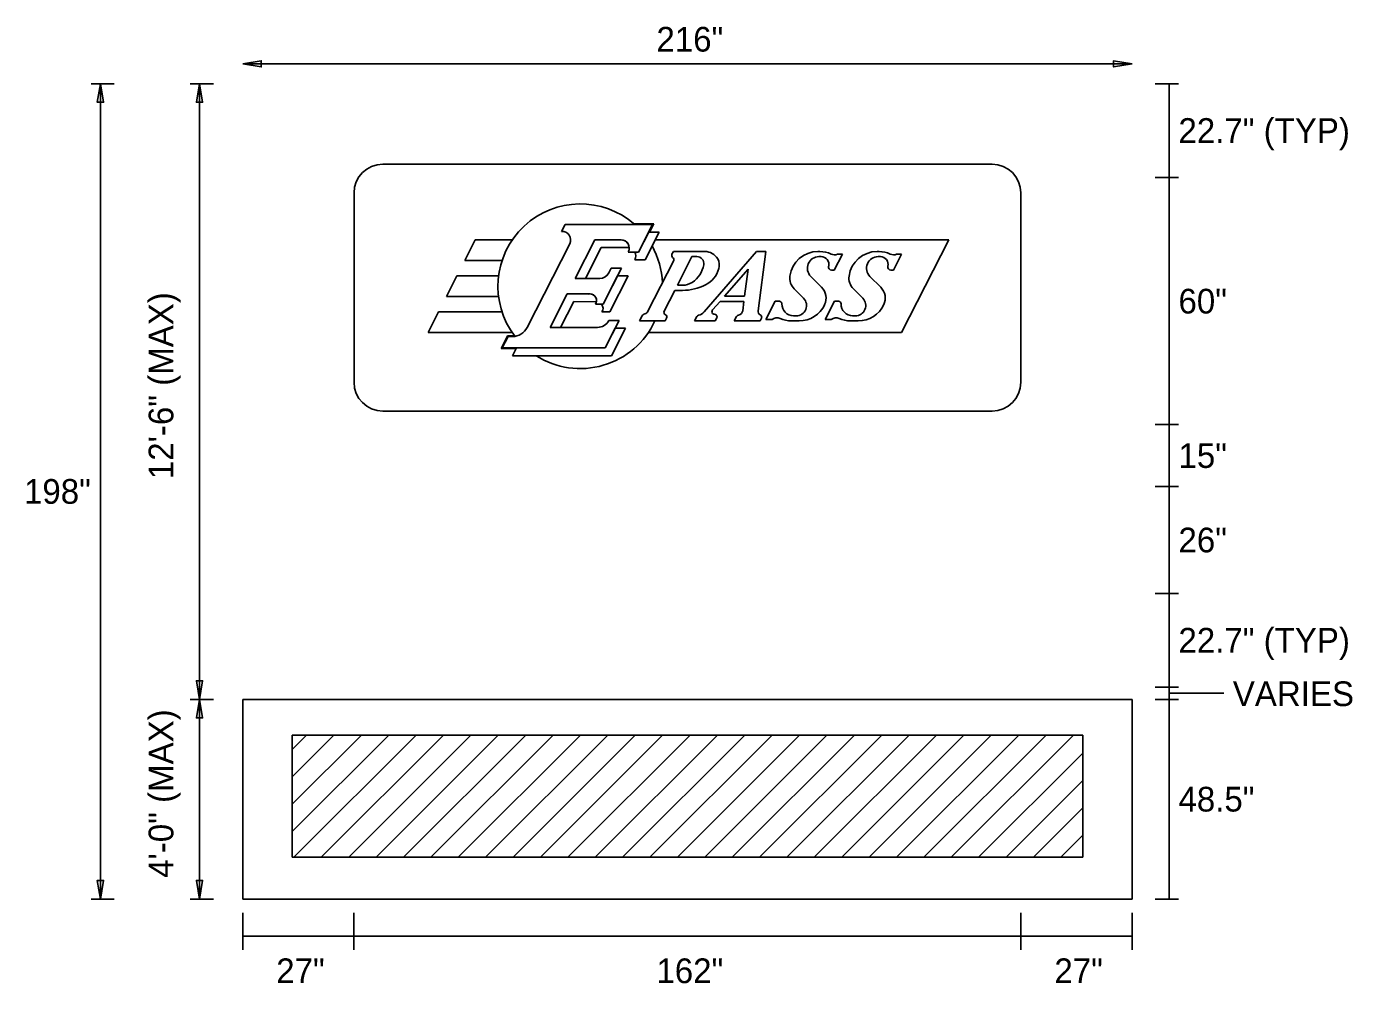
# Model space of a CAD drawing. Extents: x 10268312 to 10268706, y 2142548 to 2142786.
# Drawn here: x 10268425.68 to 10268465.55, y 2142704.58 to 2142733.35 of the extents above; entities that cross this region are included whole.
import ezdxf

# ---------------------------------------------------------------- set-up
doc = ezdxf.new("R2010")
doc.units = 0
for name, color, linetype in [('GSDims', 7, 'Continuous'), ('SignPanel', 7, 'Continuous'), ('TextMisc', 7, 'Continuous')]:
    doc.layers.add(name, color=color, linetype=linetype)

msp = doc.modelspace()

# ---------------------------------------------------------------- linework, layer by layer
at = {"layer": 'GSDims'}
for p, q in [((10268432.186, 2142732.227), (10268458.924, 2142732.227)), ((10268428.323, 2142731.624), (10268427.626, 2142731.624)), ((10268427.905, 2142707.115), (10268427.905, 2142731.624)), ((10268431.303, 2142731.624), (10268430.607, 2142731.624)), ((10268430.886, 2142713.118), (10268430.886, 2142731.624)), ((10268459.62, 2142731.624), (10268460.317, 2142731.624)), ((10268460.038, 2142728.814), (10268460.038, 2142731.624)), ((10268460.317, 2142731.624), (10268460.317, 2142731.624)), ((10268459.62, 2142728.802), (10268460.317, 2142728.802)), ((10268460.038, 2142721.377), (10268460.038, 2142728.814)), ((10268459.62, 2142721.377), (10268460.317, 2142721.377)), ((10268460.038, 2142719.518), (10268460.038, 2142721.377)), ((10268459.62, 2142719.518), (10268460.317, 2142719.518)), ((10268460.038, 2142719.518), (10268460.038, 2142716.299)), ((10268459.62, 2142716.299), (10268460.317, 2142716.299)), ((10268460.038, 2142713.489), (10268460.038, 2142716.299)), ((10268459.62, 2142713.489), (10268460.317, 2142713.489)), ((10268460.038, 2142713.118), (10268460.038, 2142713.489)), ((10268431.303, 2142713.118), (10268430.607, 2142713.118)), ((10268430.886, 2142707.115), (10268430.886, 2142713.118)), ((10268459.62, 2142713.118), (10268460.317, 2142713.118)), ((10268460.038, 2142713.304), (10268461.681, 2142713.304)), ((10268460.038, 2142707.115), (10268460.038, 2142713.118)), ((10268428.323, 2142707.115), (10268427.626, 2142707.115)), ((10268431.303, 2142707.115), (10268430.607, 2142707.115)), ((10268459.62, 2142707.115), (10268460.317, 2142707.115)), ((10268432.186, 2142706.697), (10268432.186, 2142705.583)), ((10268435.528, 2142706.697), (10268435.528, 2142705.583)), ((10268455.582, 2142706.697), (10268455.582, 2142705.583)), ((10268458.924, 2142706.697), (10268458.924, 2142705.583)), ((10268432.186, 2142706), (10268435.528, 2142706)), ((10268435.528, 2142706), (10268455.582, 2142706)), ((10268455.582, 2142706), (10268458.924, 2142706))]:
    msp.add_line(p, q, dxfattribs=at)
for points in [[(10268432.186, 2142732.227), (10268432.743, 2142732.134), (10268432.743, 2142732.319)], [(10268458.924, 2142732.227), (10268458.367, 2142732.134), (10268458.367, 2142732.319)], [(10268427.905, 2142731.624), (10268427.998, 2142731.067), (10268427.812, 2142731.067)], [(10268430.886, 2142731.624), (10268430.978, 2142731.067), (10268430.793, 2142731.067)], [(10268430.886, 2142713.118), (10268430.978, 2142713.675), (10268430.793, 2142713.675)], [(10268430.886, 2142713.118), (10268430.978, 2142712.561), (10268430.793, 2142712.561)], [(10268427.905, 2142707.115), (10268427.998, 2142707.672), (10268427.812, 2142707.672)], [(10268430.886, 2142707.115), (10268430.978, 2142707.672), (10268430.793, 2142707.672)]]:
    msp.add_lwpolyline(points, close=True, dxfattribs=at)
at = {"layer": 'SignPanel'}
for p, q in [((10268436.397, 2142729.21), (10268454.713, 2142729.21)), ((10268435.531, 2142722.651), (10268435.531, 2142728.344)), ((10268455.579, 2142728.344), (10268455.579, 2142722.651)), ((10268441.772, 2142727.187), (10268441.877, 2142727.395)), ((10268441.877, 2142727.395), (10268444.507, 2142727.395)), ((10268443.942, 2142727.418), (10268444.545, 2142727.418)), ((10268444.507, 2142727.395), (10268444.086, 2142726.567)), ((10268444.545, 2142727.418), (10268444.415, 2142727.163)), ((10268439.176, 2142726.93), (10268438.861, 2142726.312)), ((10268439.176, 2142726.93), (10268440.285, 2142726.93)), ((10268442.768, 2142726.93), (10268442.177, 2142725.77)), ((10268442.177, 2142725.77), (10268442.768, 2142726.93)), ((10268443.557, 2142726.93), (10268442.768, 2142726.93)), ((10268442.768, 2142726.93), (10268443.557, 2142726.93)), ((10268444.085, 2142726.567), (10268444.389, 2142727.163)), ((10268444.701, 2142727.163), (10268444.28, 2142726.335)), ((10268444.389, 2142727.163), (10268444.701, 2142727.163)), ((10268444.583, 2142726.93), (10268453.408, 2142726.93)), ((10268451.989, 2142724.146), (10268453.408, 2142726.93)), ((10268440.732, 2142724.297), (10268442.016, 2142726.817)), ((10268442.963, 2142726.699), (10268442.49, 2142725.77)), ((10268443.804, 2142726.699), (10268442.963, 2142726.699)), ((10268444.086, 2142726.567), (10268443.776, 2142726.567)), ((10268443.97, 2142726.567), (10268444.085, 2142726.567)), ((10268445.132, 2142726.582), (10268445.089, 2142726.5)), ((10268446.079, 2142726.582), (10268445.132, 2142726.582)), ((10268446.055, 2142724.766), (10268447.635, 2142726.582)), ((10268447.635, 2142726.582), (10268447.913, 2142726.582)), ((10268447.913, 2142726.582), (10268447.682, 2142724.802)), ((10268449.478, 2142726.582), (10268449.536, 2142726.582)), ((10268450.214, 2142726.505), (10268449.968, 2142726.022)), ((10268450.098, 2142726.505), (10268450.214, 2142726.505)), ((10268451.257, 2142726.582), (10268451.316, 2142726.582)), ((10268451.993, 2142726.505), (10268451.747, 2142726.022)), ((10268451.877, 2142726.505), (10268451.993, 2142726.505)), ((10268438.861, 2142726.312), (10268439.98, 2142726.312)), ((10268444.28, 2142726.335), (10268443.971, 2142726.335)), ((10268445.134, 2142726.29), (10268444.368, 2142724.787)), ((10268445.253, 2142725.569), (10268445.69, 2142726.428)), ((10268445.253, 2142725.569), (10268445.69, 2142726.428)), ((10268445.69, 2142726.428), (10268445.839, 2142726.428)), ((10268445.69, 2142726.428), (10268445.839, 2142726.428)), ((10268449.576, 2142726.428), (10268449.509, 2142726.428)), ((10268451.355, 2142726.428), (10268451.288, 2142726.428)), ((10268438.625, 2142725.848), (10268438.309, 2142725.229)), ((10268438.625, 2142725.848), (10268439.875, 2142725.848)), ((10268442.177, 2142725.77), (10268442.918, 2142725.77)), ((10268442.49, 2142725.77), (10268442.177, 2142725.77)), ((10268443.574, 2142726.08), (10268443.022, 2142724.997)), ((10268443.022, 2142724.997), (10268443.456, 2142725.848)), ((10268443.193, 2142725.939), (10268443.265, 2142726.08)), ((10268443.768, 2142725.848), (10268443.217, 2142724.765)), ((10268443.265, 2142726.08), (10268443.574, 2142726.08)), ((10268443.456, 2142725.848), (10268443.768, 2142725.848)), ((10268447.376, 2142726.049), (10268446.669, 2142725.236)), ((10268447.376, 2142726.049), (10268446.669, 2142725.236)), ((10268447.27, 2142725.236), (10268447.376, 2142726.049)), ((10268447.27, 2142725.236), (10268447.376, 2142726.049)), ((10268449.263, 2142725.834), (10268449.587, 2142725.509)), ((10268449.968, 2142726.022), (10268449.891, 2142726.022)), ((10268451.042, 2142725.834), (10268451.367, 2142725.509)), ((10268451.747, 2142726.022), (10268451.669, 2142726.022)), ((10268441.941, 2142725.306), (10268441.429, 2142724.301)), ((10268441.429, 2142724.301), (10268441.941, 2142725.306)), ((10268442.62, 2142725.306), (10268441.941, 2142725.306)), ((10268441.941, 2142725.306), (10268442.591, 2142725.304)), ((10268444.854, 2142724.787), (10268445.174, 2142725.414)), ((10268445.174, 2142725.414), (10268445.406, 2142725.414)), ((10268445.406, 2142725.569), (10268445.253, 2142725.569)), ((10268445.406, 2142725.569), (10268445.253, 2142725.569)), ((10268449.045, 2142725.177), (10268448.767, 2142725.455)), ((10268450.824, 2142725.177), (10268450.545, 2142725.455)), ((10268438.309, 2142725.229), (10268439.875, 2142725.229)), ((10268442.135, 2142725.074), (10268441.741, 2142724.301)), ((10268442.818, 2142725.071), (10268442.135, 2142725.074)), ((10268443.022, 2142724.997), (10268442.789, 2142724.997)), ((10268442.974, 2142724.997), (10268443.022, 2142724.997)), ((10268446.535, 2142725.082), (10268446.311, 2142724.824)), ((10268447.254, 2142725.082), (10268446.535, 2142725.082)), ((10268446.669, 2142725.236), (10268447.27, 2142725.236)), ((10268446.669, 2142725.236), (10268447.27, 2142725.236)), ((10268447.218, 2142724.802), (10268447.254, 2142725.082)), ((10268447.912, 2142724.533), (10268448.193, 2142725.084)), ((10268448.193, 2142725.084), (10268448.317, 2142725.084)), ((10268449.691, 2142724.533), (10268449.972, 2142725.084)), ((10268449.972, 2142725.084), (10268450.096, 2142725.084)), ((10268438.073, 2142724.765), (10268437.758, 2142724.146)), ((10268438.073, 2142724.765), (10268439.98, 2142724.765)), ((10268443.217, 2142724.765), (10268442.985, 2142724.765)), ((10268443.501, 2142724.509), (10268443.08, 2142723.682)), ((10268443.191, 2142724.509), (10268443.501, 2142724.509)), ((10268444.18, 2142724.63), (10268444.11, 2142724.494)), ((10268444.884, 2142724.494), (10268444.926, 2142724.577)), ((10268445.77, 2142724.494), (10268445.838, 2142724.626)), ((10268446.435, 2142724.583), (10268446.389, 2142724.494)), ((10268446.964, 2142724.494), (10268447.033, 2142724.628)), ((10268447.778, 2142724.574), (10268447.738, 2142724.494)), ((10268448.1, 2142724.533), (10268447.912, 2142724.533)), ((10268448.742, 2142724.649), (10268448.826, 2142724.649)), ((10268449.879, 2142724.533), (10268449.691, 2142724.533)), ((10268450.521, 2142724.649), (10268450.605, 2142724.649)), ((10268437.758, 2142724.146), (10268440.285, 2142724.146)), ((10268441.429, 2142724.301), (10268442.849, 2142724.301)), ((10268441.741, 2142724.301), (10268441.429, 2142724.301)), ((10268443.08, 2142723.682), (10268443.383, 2142724.277)), ((10268443.695, 2142724.277), (10268443.274, 2142723.45)), ((10268443.383, 2142724.277), (10268443.695, 2142724.277)), ((10268444.11, 2142724.494), (10268444.884, 2142724.494)), ((10268444.378, 2142724.146), (10268451.989, 2142724.146)), ((10268446.389, 2142724.494), (10268445.77, 2142724.494)), ((10268447.738, 2142724.494), (10268446.964, 2142724.494)), ((10268448.909, 2142724.494), (10268448.677, 2142724.494)), ((10268450.688, 2142724.494), (10268450.455, 2142724.494)), ((10268439.953, 2142723.662), (10268440.149, 2142724.047)), ((10268439.986, 2142723.682), (10268440.161, 2142724.026)), ((10268440.149, 2142724.047), (10268440.291, 2142724.047)), ((10268440.161, 2142724.026), (10268440.291, 2142724.026)), ((10268440.403, 2142723.662), (10268439.953, 2142723.662)), ((10268443.08, 2142723.682), (10268439.986, 2142723.682)), ((10268440.295, 2142723.45), (10268440.413, 2142723.682)), ((10268443.274, 2142723.45), (10268440.295, 2142723.45)), ((10268440.413, 2142723.682), (10268443.08, 2142723.682)), ((10268454.713, 2142721.785), (10268436.397, 2142721.785)), ((10268458.924, 2142713.118), (10268432.186, 2142713.118)), ((10268432.186, 2142713.118), (10268432.186, 2142707.115)), ((10268458.924, 2142707.115), (10268458.924, 2142713.118)), ((10268432.186, 2142707.115), (10268458.924, 2142707.115))]:
    msp.add_line(p, q, dxfattribs=at)
for centre, radius, start, end in [((10268436.397, 2142728.344), 0.866, 90, 180), ((10268454.713, 2142728.344), 0.866, 0, 90), ((10268442.331, 2142725.538), 2.475, 48.5904, 217.4727), ((10268441.788, 2142726.932), 0.255, 332.9998, 93.8045), ((10268443.557, 2142726.683), 0.248, 332.2089, 90), ((10268443.557, 2142726.683), 0.248, 3.5833, 90), ((10268443.751, 2142726.451), 0.248, 332.2089, 27.9127), ((10268442.331, 2142725.538), 2.475, 2.4236, 29.2771), ((10268445.158, 2142726.465), 0.0773, 152.9784, 231.1602), ((10268446.079, 2142726.141), 0.441, 29.4315, 90), ((10268449.478, 2142725.731), 0.851, 90, 172.3089), ((10268449.536, 2142725.809), 0.773, 64.0896, 90), ((10268449.976, 2142726.713), 0.232, 244.0896, 292.0347), ((10268450.098, 2142726.412), 0.0928, 90, 112.0347), ((10268451.257, 2142725.731), 0.851, 90, 172.3089), ((10268451.315, 2142725.809), 0.773, 64.0896, 90), ((10268451.755, 2142726.713), 0.232, 244.0896, 292.0347), ((10268451.877, 2142726.412), 0.0928, 90, 112.0347), ((10268445.051, 2142726.332), 0.0928, 333.0027, 51.1602), ((10268445.281, 2142726.306), 0.773, 302.4206, 351.076), ((10268445.281, 2142726.306), 0.773, 302.4206, 351.076), ((10268445.839, 2142726.219), 0.209, 351.076, 90), ((10268445.839, 2142726.219), 0.209, 351.076, 90), ((10268446.126, 2142726.168), 0.387, 344.7074, 29.4315), ((10268449.509, 2142726.08), 0.348, 90, 225), ((10268449.576, 2142726.196), 0.232, 345.6915, 90), ((10268449.89, 2142726.115), 0.0928, 165.6915, 270), ((10268451.288, 2142726.08), 0.348, 90, 225), ((10268451.355, 2142726.196), 0.232, 345.6915, 90), ((10268451.669, 2142726.115), 0.0928, 165.6915, 270), ((10268442.917, 2142726.08), 0.309, 270, 332.9883), ((10268445.753, 2142726.27), 0.773, 296.6431, 344.7074), ((10268449.094, 2142725.783), 0.464, 172.3089, 225), ((10268450.873, 2142725.783), 0.464, 172.3089, 225), ((10268442.62, 2142725.105), 0.201, 350.3502, 98.3344), ((10268442.62, 2142725.105), 0.201, 327.421, 90), ((10268445.406, 2142726.11), 0.541, 270, 302.4206), ((10268445.406, 2142726.11), 0.541, 270, 302.4206), ((10268445.406, 2142726.961), 1.547, 270, 296.6431), ((10268449.259, 2142725.181), 0.464, 334.95, 45), ((10268451.038, 2142725.181), 0.464, 334.95, 45), ((10268442.815, 2142724.873), 0.201, 327.421, 37.9799), ((10268448.317, 2142725.007), 0.0773, 358.6664, 90), ((10268448.742, 2142724.997), 0.348, 178.6665, 270), ((10268448.826, 2142724.958), 0.309, 270, 45), ((10268448.909, 2142725.345), 0.851, 270, 334.95), ((10268450.096, 2142725.007), 0.0773, 358.6664, 90), ((10268450.521, 2142724.997), 0.348, 178.6665, 270), ((10268450.605, 2142724.958), 0.309, 270, 45), ((10268450.688, 2142725.345), 0.851, 270, 334.95), ((10268442.848, 2142724.687), 0.387, 270, 332.5096), ((10268444.318, 2142724.56), 0.155, 106.4317, 152.9742), ((10268444.23, 2142724.857), 0.155, 286.4317, 332.9959), ((10268444.923, 2142724.752), 0.0773, 152.9884, 244.7832), ((10268444.857, 2142724.612), 0.0773, 333.0239, 64.7832), ((10268445.907, 2142724.591), 0.0773, 102.7162, 153.0239), ((10268445.821, 2142724.968), 0.309, 282.7162, 318.9966), ((10268446.369, 2142724.773), 0.0773, 138.9824, 268.6869), ((10268446.366, 2142724.618), 0.0773, 332.9784, 88.6869), ((10268447.101, 2142724.593), 0.0773, 99.2397, 153.0239), ((10268447.064, 2142724.822), 0.155, 279.2397, 352.5632), ((10268447.804, 2142724.786), 0.124, 172.5884, 241.8673), ((10268447.709, 2142724.609), 0.0773, 332.9784, 61.8673), ((10268448.248, 2142724.375), 0.217, 64.3795, 133.1892), ((10268448.676, 2142725.267), 0.773, 244.3795, 270), ((10268450.027, 2142724.375), 0.217, 64.3795, 133.1892), ((10268450.455, 2142725.267), 0.773, 244.3795, 270), ((10268440.291, 2142724.521), 0.495, 270, 332.9991), ((10268442.331, 2142725.538), 2.475, 237.5383, 335.047), ((10268440.291, 2142724.521), 0.475, 270, 277.5038), ((10268436.397, 2142722.651), 0.866, 180, 270), ((10268454.713, 2142722.651), 0.866, 270, 360)]:
    msp.add_arc(centre, radius, start, end, dxfattribs=at)
at = {"layer": 'TextMisc'}
for p, q in [((10268433.672, 2142711.612), (10268434.103, 2142712.042)), ((10268433.672, 2142710.79), (10268434.926, 2142712.042)), ((10268433.672, 2142709.968), (10268435.75, 2142712.042)), ((10268433.672, 2142709.147), (10268436.573, 2142712.042)), ((10268433.672, 2142712.042), (10268457.439, 2142712.042)), ((10268433.672, 2142712.042), (10268433.672, 2142708.376)), ((10268433.722, 2142708.376), (10268437.397, 2142712.042)), ((10268434.546, 2142708.376), (10268438.22, 2142712.042)), ((10268435.369, 2142708.376), (10268439.044, 2142712.042)), ((10268436.193, 2142708.376), (10268439.867, 2142712.042)), ((10268437.016, 2142708.376), (10268440.691, 2142712.042)), ((10268437.84, 2142708.376), (10268441.514, 2142712.042)), ((10268438.663, 2142708.376), (10268442.338, 2142712.042)), ((10268439.487, 2142708.376), (10268443.161, 2142712.042)), ((10268440.31, 2142708.376), (10268443.985, 2142712.042)), ((10268441.134, 2142708.376), (10268444.808, 2142712.042)), ((10268441.957, 2142708.376), (10268445.632, 2142712.042)), ((10268442.781, 2142708.376), (10268446.455, 2142712.042)), ((10268443.604, 2142708.376), (10268447.278, 2142712.042)), ((10268444.428, 2142708.376), (10268448.102, 2142712.042)), ((10268445.251, 2142708.376), (10268448.925, 2142712.042)), ((10268446.075, 2142708.376), (10268449.749, 2142712.042)), ((10268446.898, 2142708.376), (10268450.572, 2142712.042)), ((10268447.722, 2142708.376), (10268451.396, 2142712.042)), ((10268448.545, 2142708.376), (10268452.219, 2142712.042)), ((10268449.369, 2142708.376), (10268453.043, 2142712.042)), ((10268450.192, 2142708.376), (10268453.866, 2142712.042)), ((10268451.016, 2142708.376), (10268454.69, 2142712.042)), ((10268451.839, 2142708.376), (10268455.513, 2142712.042)), ((10268452.662, 2142708.376), (10268456.337, 2142712.042)), ((10268453.486, 2142708.376), (10268457.16, 2142712.042)), ((10268457.439, 2142712.042), (10268457.439, 2142708.376)), ((10268454.309, 2142708.376), (10268457.439, 2142711.498)), ((10268455.133, 2142708.376), (10268457.439, 2142710.676)), ((10268455.956, 2142708.376), (10268457.439, 2142709.855)), ((10268456.78, 2142708.376), (10268457.439, 2142709.033)), ((10268433.672, 2142708.376), (10268457.439, 2142708.376))]:
    msp.add_line(p, q, dxfattribs=at)

# ---------------------------------------------------------------- texts
at = {"layer": 'GSDims'}
for s, height, p in [('216"', 0.7427, (10268444.622, 2142732.592)), ('22.7" (TYP)', 0.74272, (10268460.317, 2142729.848)), ('60"', 0.7427, (10268460.317, 2142724.718)), ('15"', 0.7427, (10268460.317, 2142720.076)), ('26"', 0.7427, (10268460.317, 2142717.537)), ('22.7" (TYP)', 0.74272, (10268460.317, 2142714.523)), ('VARIES', 0.7427, (10268461.951, 2142712.915)), ('48.5"', 0.7427, (10268460.317, 2142709.745)), ('27"', 0.7427, (10268433.191, 2142704.586)), ('162"', 0.7427, (10268444.622, 2142704.586)), ('27"', 0.7427, (10268456.587, 2142704.586))]:
    msp.add_text(s, height=height, dxfattribs=at).set_placement(p)
for s, height, rotation, p in [('12\'-6" (MAX)', 0.74272, 90, (10268430.098, 2142719.738)), ('198"', 0.7427, 360, (10268425.608, 2142718.998)), ('4\'-0" (MAX)', 0.74272, 90, (10268430.098, 2142707.75))]:
    msp.add_text(s, height=height, rotation=rotation, dxfattribs=at).set_placement(p)

doc.saveas('drawing.dxf')
